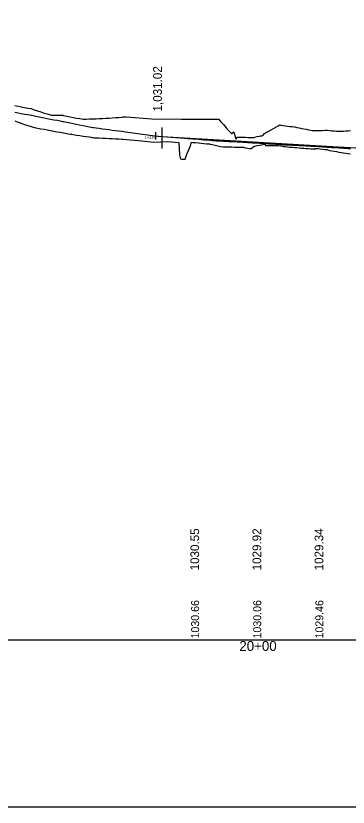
# Model space of a CAD drawing. Extents: x 1590191 to 1593577, y 1108634 to 1115609.
# Drawn here: x 1591081 to 1591349, y 1114509 to 1115146 of the extents above; entities that cross this region are included whole.
import ezdxf

# ---------------------------------------------------------------- set-up
doc = ezdxf.new("R2010")
doc.units = 0
for name, color, linetype in [('BR_EXIST_GROUND_LT', 7, 'Continuous'), ('BR_EXIST_GROUND_RT', 7, 'Continuous'), ('BR_USER NOTES', 7, 'Continuous'), ('RD_DDB_Profile_EX', 7, 'Continuous'), ('RD_DDB_Profile_Lbl', 7, 'Continuous'), ('RD_DDB_Profile_PR', 7, 'Continuous'), ('RD_DDB_StaTX', 7, 'Continuous'), ('RD_DDB_StripGrade', 7, 'Continuous'), ('RD_GPK_Profile_Cell', 7, 'Continuous'), ('RD_SHT_ShtClip', 7, 'Continuous')]:
    doc.layers.add(name, color=color, linetype=linetype)

msp = doc.modelspace()

# ---------------------------------------------------------------- linework, layer by layer
at = {"layer": 'BR_EXIST_GROUND_LT'}
msp.add_lwpolyline([(1591080.58, 1115060.95), (1591083.2, 1115060.03), (1591084.93, 1115059.43), (1591085.5, 1115059.27), (1591085.82, 1115059.16), (1591088.44, 1115058.26), (1591091.05, 1115057.37), (1591093.67, 1115056.48), (1591095.51, 1115055.86), (1591096.29, 1115055.72), (1591096.82, 1115055.63), (1591098.91, 1115055.23), (1591101.53, 1115054.73), (1591104.15, 1115054.24), (1591106.77, 1115053.75), (1591109.39, 1115053.27), (1591112, 1115052.79), (1591114.62, 1115052.32), (1591117.24, 1115051.85), (1591119.94, 1115051.36), (1591122.48, 1115050.92), (1591125.1, 1115050.46), (1591126.43, 1115050.23), (1591127.72, 1115050.03), (1591130.34, 1115049.63), (1591132.95, 1115049.24), (1591135.57, 1115048.85), (1591138.19, 1115048.48), (1591140.81, 1115048.12), (1591141.94, 1115047.96), (1591142.7, 1115047.74), (1591143.43, 1115047.65), (1591144.5, 1115047.52), (1591146.05, 1115047.43), (1591148.67, 1115047.29), (1591151.29, 1115047.15), (1591153.91, 1115047.02), (1591156.52, 1115046.89), (1591159.14, 1115046.78), (1591161.76, 1115046.66), (1591164.38, 1115046.55), (1591167, 1115046.45), (1591167.9, 1115046.42), (1591182.94, 1115044.93), (1591192.48, 1115043.91), (1591203.91, 1115044.57), (1591212.76, 1115043.57), (1591213.18, 1115033.82), (1591213.9, 1115030.4), (1591215.23, 1115030.28), (1591217.21, 1115030.21), (1591217.77, 1115030.19), (1591218.86, 1115033.36), (1591219.45, 1115034.83), (1591221.69, 1115040.51), (1591223, 1115043.84), (1591223.92, 1115043.75), (1591226.16, 1115043.53), (1591228.4, 1115043.32), (1591230.64, 1115043.1), (1591232.88, 1115042.89), (1591235.12, 1115042.69), (1591237.36, 1115042.48), (1591238.04, 1115042.42), (1591239.6, 1115042.01), (1591241.84, 1115041.44), (1591244.08, 1115040.87), (1591246.32, 1115040.36), (1591248.56, 1115040.28), (1591250.8, 1115040.2), (1591253.04, 1115040.13), (1591255.28, 1115040.06), (1591257.52, 1115040), (1591259.76, 1115039.94), (1591262, 1115039.88), (1591264.24, 1115039.83), (1591264.79, 1115039.82), (1591266.48, 1115039.48), (1591268.35, 1115038.98), (1591269.48, 1115038.69), (1591270.23, 1115038.72), (1591270.87, 1115038.75), (1591272.1, 1115039.69), (1591273.38, 1115040.68), (1591273.97, 1115040.79), (1591275.85, 1115041.13), (1591277.72, 1115041.48), (1591279.6, 1115041.84), (1591281.49, 1115042.2), (1591281.86, 1115042.26), (1591282.59, 1115041.24), (1591283.34, 1115041.23), (1591285.22, 1115041.21), (1591287.09, 1115041.2), (1591288.97, 1115041.19), (1591290.84, 1115041.17), (1591292.71, 1115041.15), (1591294.59, 1115040.88), (1591296.46, 1115040.61), (1591296.93, 1115040.55), (1591298.34, 1115040.38), (1591300.21, 1115040.16), (1591301.53, 1115040.01), (1591302.08, 1115039.96), (1591303.96, 1115039.81), (1591305.83, 1115039.65), (1591307.71, 1115039.5), (1591309.58, 1115039.35), (1591311.45, 1115039.21), (1591313.38, 1115039.06), (1591315.2, 1115038.91), (1591317.08, 1115038.76), (1591318.95, 1115038.61), (1591320.82, 1115038.46), (1591321.57, 1115038.4), (1591321.97, 1115038.12), (1591322.49, 1115038.94), (1591324.57, 1115038.71), (1591326.45, 1115038.5), (1591328.32, 1115038.29), (1591330.19, 1115038.09), (1591332.11, 1115037.88), (1591332.7, 1115037.74), (1591333.94, 1115037.31), (1591335.82, 1115036.96), (1591337.69, 1115036.62), (1591339.56, 1115036.3), (1591341.44, 1115035.99), (1591343.31, 1115035.69), (1591345.19, 1115035.41), (1591347.06, 1115035.14), (1591348.93, 1115034.88), (1591350.81, 1115034.64)], dxfattribs=at)
at = {"layer": 'BR_EXIST_GROUND_RT'}
msp.add_lwpolyline([(1591080.58, 1115073.53), (1591083.2, 1115072.91), (1591085.82, 1115072.33), (1591086.47, 1115072.19), (1591088.44, 1115071.81), (1591091.05, 1115071.33), (1591093.67, 1115070.88), (1591096.29, 1115069.95), (1591098.91, 1115069.05), (1591101.53, 1115068.19), (1591104.15, 1115067.36), (1591106.77, 1115066.58), (1591109.39, 1115065.82), (1591110.03, 1115065.65), (1591112, 1115065.62), (1591114.62, 1115065.6), (1591117.24, 1115065.62), (1591119.18, 1115065.65), (1591119.86, 1115065.49), (1591122.48, 1115064.91), (1591125.1, 1115064.36), (1591127.72, 1115063.84), (1591130.34, 1115063.34), (1591132.95, 1115062.87), (1591135.57, 1115062.43), (1591135.97, 1115062.37), (1591138.19, 1115062.47), (1591140.81, 1115062.6), (1591142.38, 1115062.7), (1591143.43, 1115062.71), (1591146.05, 1115062.78), (1591148.67, 1115062.86), (1591151.29, 1115062.97), (1591153.91, 1115063.1), (1591156.52, 1115063.25), (1591159.14, 1115063.43), (1591161.76, 1115063.63), (1591164.38, 1115063.85), (1591167.13, 1115064.1), (1591167.92, 1115064.19), (1591170.41, 1115064.43), (1591190.89, 1115062.74), (1591214.74, 1115062.48), (1591217.21, 1115062.39), (1591217.56, 1115062.38), (1591219.45, 1115062.36), (1591221.69, 1115062.34), (1591223.92, 1115062.33), (1591226.16, 1115062.32), (1591228.4, 1115062.31), (1591230.64, 1115062.31), (1591232.88, 1115062.31), (1591235.12, 1115062.32), (1591237.36, 1115062.33), (1591239.6, 1115062.35), (1591241.95, 1115062.37), (1591244.08, 1115062.43), (1591244.81, 1115062.4), (1591246.32, 1115060.65), (1591248.56, 1115058.08), (1591250.8, 1115055.52), (1591253.04, 1115052.97), (1591254.96, 1115050.81), (1591255.28, 1115051.01), (1591257.04, 1115052.12), (1591257.52, 1115050.38), (1591258.63, 1115046.4), (1591259.92, 1115047.87), (1591262, 1115047.84), (1591264.24, 1115047.82), (1591266.48, 1115047.8), (1591268.35, 1115047.79), (1591270.23, 1115047.79), (1591272.1, 1115047.79), (1591273.22, 1115047.79), (1591273.97, 1115047.95), (1591275.85, 1115048.34), (1591277.72, 1115048.73), (1591278.56, 1115048.91), (1591279.6, 1115049.13), (1591279.95, 1115049.21), (1591280.41, 1115049.35), (1591281.73, 1115051), (1591283.34, 1115051.84), (1591285.22, 1115052.84), (1591287.09, 1115053.85), (1591288.97, 1115054.88), (1591290.84, 1115055.93), (1591292.71, 1115057), (1591293.98, 1115057.73), (1591294.59, 1115057.63), (1591296.46, 1115057.34), (1591298.34, 1115057.08), (1591300.21, 1115056.83), (1591302.08, 1115056.61), (1591303.96, 1115056.4), (1591305.83, 1115056.22), (1591306.14, 1115056.19), (1591307.71, 1115055.82), (1591309.58, 1115055.4), (1591311.45, 1115055), (1591313.33, 1115054.61), (1591315.2, 1115054.25), (1591317.08, 1115053.9), (1591318.95, 1115053.57), (1591319.95, 1115053.4), (1591320.82, 1115053.39), (1591322.7, 1115053.37), (1591324.57, 1115053.37), (1591326.45, 1115053.39), (1591328.32, 1115053.43), (1591330.19, 1115053.49), (1591331.5, 1115053.54), (1591332.07, 1115053.48), (1591333.94, 1115053.29), (1591335.82, 1115053.12), (1591337.69, 1115052.97), (1591339.56, 1115052.83), (1591341.5, 1115052.71), (1591343.31, 1115052.79), (1591345.19, 1115052.89), (1591347.06, 1115053), (1591348.93, 1115053.14), (1591350.81, 1115053.28)], dxfattribs=at)
at = {"layer": 'BR_USER NOTES'}
for p, q in [((1591199.01, 1115055.63), (1591199.01, 1115038.9)), ((1591194.01, 1115051.96), (1591194.01, 1115045.98)), ((1591194.01, 1115049), (1591199.01, 1115048.59))]:
    msp.add_line(p, q, dxfattribs=at)
at = {"layer": 'RD_DDB_Profile_EX'}
msp.add_lwpolyline([(1591080.58, 1115067.98), (1591083.2, 1115067.51), (1591085.82, 1115067.04), (1591088.44, 1115066.56), (1591091.05, 1115066.09), (1591093.67, 1115065.61), (1591094.23, 1115065.51), (1591096.29, 1115065.1), (1591098.91, 1115064.59), (1591101.53, 1115064.07), (1591104.15, 1115063.55), (1591106.77, 1115063.04), (1591109.39, 1115062.52), (1591112, 1115062), (1591114.62, 1115061.49), (1591117.24, 1115060.97), (1591119.08, 1115060.61), (1591119.86, 1115060.46), (1591122.48, 1115059.94), (1591125.1, 1115059.43), (1591127.72, 1115058.91), (1591130.34, 1115058.4), (1591132.74, 1115057.92), (1591135.57, 1115057.36), (1591138.19, 1115056.83), (1591140.81, 1115056.3), (1591143.47, 1115055.76), (1591144.26, 1115055.65), (1591146.05, 1115055.42), (1591148.67, 1115055.07), (1591151.29, 1115054.73), (1591153.91, 1115054.38), (1591156.52, 1115054.03), (1591159.14, 1115053.68), (1591161.76, 1115053.33), (1591164.38, 1115052.98), (1591167, 1115052.63), (1591168.46, 1115052.43), (1591169.85, 1115052.24), (1591193.35, 1115049.05), (1591195.91, 1115048.84), (1591217.21, 1115047.18), (1591218.4, 1115047.09), (1591219.65, 1115046.98), (1591221.69, 1115046.82), (1591223.92, 1115046.65), (1591226.16, 1115046.47), (1591228.4, 1115046.29), (1591230.64, 1115046.11), (1591232.88, 1115045.92), (1591235.12, 1115045.74), (1591237.36, 1115045.55), (1591239.6, 1115045.36), (1591241.84, 1115045.17), (1591242.84, 1115045.09), (1591244.08, 1115045.03), (1591246.32, 1115044.92), (1591248.56, 1115044.8), (1591250.8, 1115044.69), (1591253.04, 1115044.57), (1591255.14, 1115044.46), (1591257.52, 1115044.33), (1591259.76, 1115044.19), (1591262, 1115044.06), (1591264.24, 1115043.93), (1591266.48, 1115043.8), (1591268.05, 1115043.71), (1591268.35, 1115043.69), (1591270.23, 1115043.58), (1591272.1, 1115043.47), (1591273.97, 1115043.36), (1591275.85, 1115043.25), (1591277.72, 1115043.14), (1591279.6, 1115043.03), (1591281.47, 1115042.92), (1591283.34, 1115042.8), (1591285.22, 1115042.69), (1591287.09, 1115042.58), (1591288.8, 1115042.48), (1591290.84, 1115042.34), (1591292.82, 1115042.21), (1591294.59, 1115042.09), (1591296.46, 1115041.96), (1591297.03, 1115041.93), (1591297.94, 1115041.87), (1591298.34, 1115041.85), (1591300.21, 1115041.77), (1591302.08, 1115041.68), (1591303.96, 1115041.59), (1591305.83, 1115041.5), (1591307.71, 1115041.41), (1591309.58, 1115041.31), (1591311.45, 1115041.22), (1591313.33, 1115041.12), (1591315.2, 1115041.02), (1591317.08, 1115040.92), (1591318.95, 1115040.82), (1591320.82, 1115040.72), (1591321.86, 1115040.66), (1591322.7, 1115040.6), (1591324.58, 1115040.45), (1591326.45, 1115040.34), (1591328.32, 1115040.23), (1591330.19, 1115040.11), (1591332.07, 1115039.99), (1591333.94, 1115039.87), (1591335.82, 1115039.75), (1591337.69, 1115039.62), (1591339.56, 1115039.49), (1591341.44, 1115039.37), (1591343.31, 1115039.24), (1591345.19, 1115039.12), (1591347.06, 1115038.99), (1591348.93, 1115038.86), (1591350.81, 1115038.73)], dxfattribs=at)
at = {"layer": 'RD_DDB_Profile_PR'}
msp.add_line((1591199.01, 1115048.59), (1591379.01, 1115037.79), dxfattribs=at)
at = {"layer": 'RD_GPK_Profile_Cell'}
msp.add_line((1590279.01, 1114643.47), (1593576.82, 1114643.47), dxfattribs=at)
at = {"layer": 'RD_SHT_ShtClip'}
msp.add_lwpolyline([(1590679.01, 1115608.73), (1592479.01, 1115608.73), (1592479.01, 1114508.73), (1590679.01, 1114508.73)], close=True, dxfattribs=at)

# ---------------------------------------------------------------- texts
at = {"layer": 'BR_USER NOTES'}
msp.add_text('-1.6120', height=2, dxfattribs=at).set_placement((1591184.27, 1115046.75))
at = {"layer": 'RD_DDB_Profile_Lbl'}
msp.add_text('1,031.02', height=7, rotation=90, dxfattribs=at).set_placement((1591199.01, 1115068.59))
at = {"layer": 'RD_DDB_StaTX'}
msp.add_text('20+00', height=8, dxfattribs=at).set_placement((1591261.42, 1114634.47))
at = {"layer": 'RD_DDB_StripGrade'}
for s, height, p in [('1030.55', 7, (1591229.01, 1114699.26)), ('1029.92', 7, (1591279.01, 1114699.26)), ('1029.34', 7, (1591329.01, 1114699.26)), ('1030.66', 6.4, (1591229.01, 1114644.47)), ('1030.06', 6.4, (1591279.01, 1114644.47)), ('1029.46', 6.4, (1591329.01, 1114644.47))]:
    msp.add_text(s, height=height, rotation=90, dxfattribs=at).set_placement(p)

doc.saveas('drawing.dxf')
